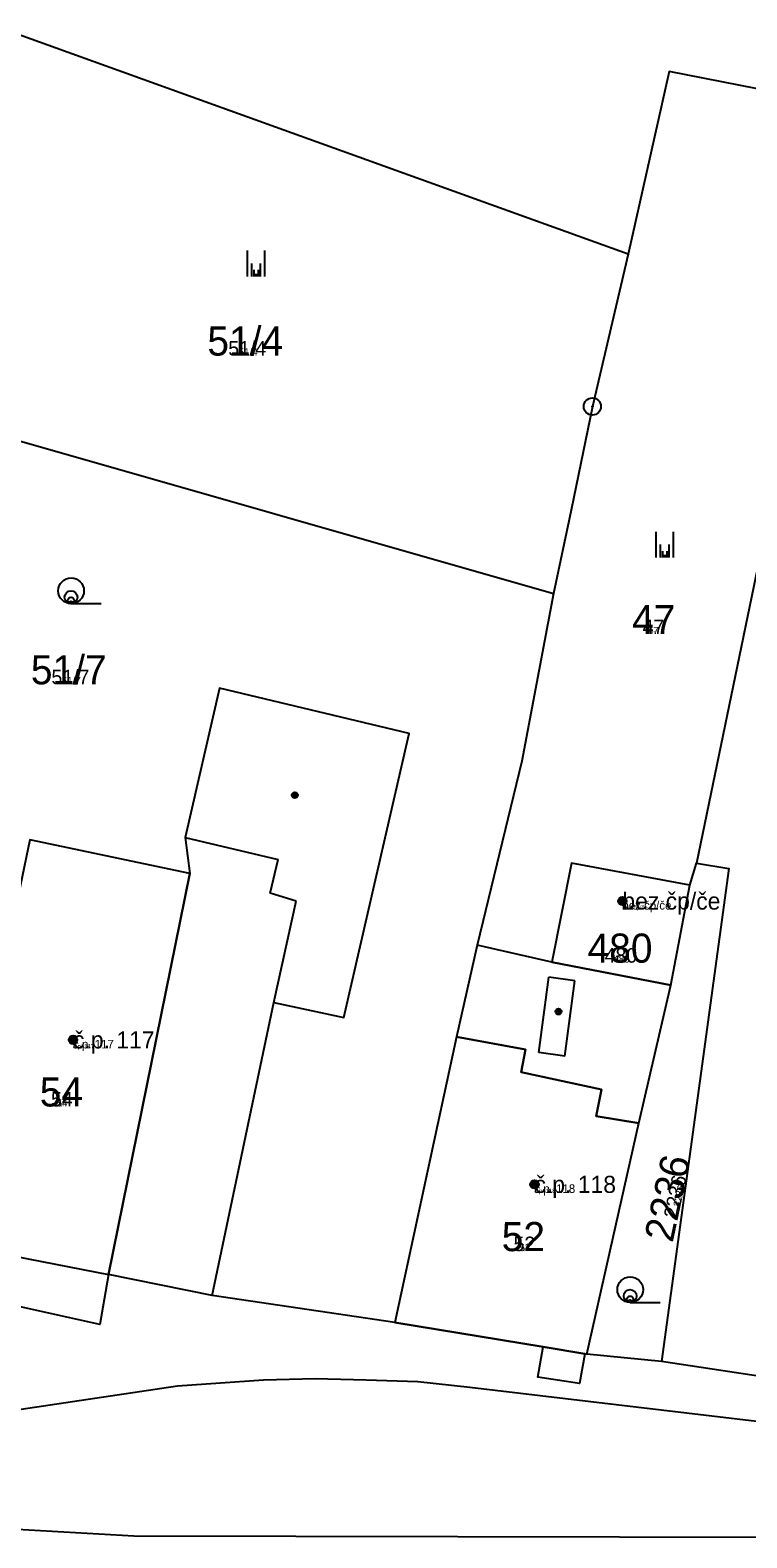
# Model space of a CAD drawing. Extents: x -744652 to -739090, y -980828 to -975855.
# Drawn here: x -742712.9 to -742671.1, y -978620.9 to -978532.9 of the extents above; entities that cross this region are included whole.
import ezdxf

# ---------------------------------------------------------------- set-up
doc = ezdxf.new("R2010")
doc.units = 0
for name, color, linetype in [('KAT_02_hranice parcel', 7, 'Continuous'), ('KAT_03_1000_st čísla parcelní', 7, 'Continuous'), ('KAT_03_1000_čísla parcelní', 7, 'Continuous'), ('KAT_03_1000_čísla popisná', 7, 'Continuous'), ('KAT_03_100_st čísla parcelní', 7, 'Continuous'), ('KAT_03_100_čísla parcelní', 7, 'Continuous'), ('KAT_03_100_čísla popisná', 7, 'Continuous'), ('KAT_03_250_st čísla parcelní', 7, 'Continuous'), ('KAT_03_250_čísla parcelní', 7, 'Continuous'), ('KAT_03_250_čísla popisná', 7, 'Continuous'), ('KAT_03_500_st čísla parcelní', 7, 'Continuous'), ('KAT_03_500_čísla parcelní', 7, 'Continuous'), ('KAT_03_500_čísla popisná', 7, 'Continuous'), ('KAT_04_vnitřní kresba', 7, 'Continuous'), ('KAT_05_1000_značky kultur', 7, 'Continuous'), ('KAT_05_100_značky kultur', 7, 'Continuous'), ('KAT_05_250_značky kultur', 7, 'Continuous'), ('KAT_05_500_značky kultur', 7, 'Continuous'), ('KAT_07_1000_značky budov', 7, 'Continuous'), ('KAT_07_100_značky budov', 7, 'Continuous'), ('KAT_07_500_značky budov', 7, 'Continuous'), ('KAT_10_věcná břemena', 7, 'Continuous'), ('KAT_11_značky bodu BP', 7, 'Continuous'), ('KAT_14_plocha_budovy', 7, 'Continuous')]:
    doc.layers.add(name, color=color, linetype=linetype)

msp = doc.modelspace()

# ---------------------------------------------------------------- linework, layer by layer
at = {"layer": 'KAT_02_hranice parcel'}
for p, q in [((-742678.03, -978545.97), (-742714.32, -978532.88)), ((-742720.83, -978554.79), (-742682.38, -978565.78)), ((-742674.42, -978582.82), (-742674.04, -978581.54)), ((-742675.53, -978588.66), (-742674.42, -978582.82)), ((-742682.48, -978587.32), (-742686.84, -978586.32)), ((-742675.53, -978588.66), (-742682.48, -978587.32)), ((-742702.3, -978606.79), (-742708.35, -978605.57)), ((-742691.64, -978608.37), (-742702.3, -978606.79)), ((-742676.07, -978610.64), (-742680.43, -978610.21)), ((-742670.16, -978611.55), (-742676.07, -978610.64))]:
    msp.add_line(p, q, dxfattribs=at)
for points in [[(-742655.01, -978539.34), (-742675.63, -978535.29), (-742678.03, -978545.97)], [(-742655.23, -978540.96), (-742665.24, -978538.98), (-742674.04, -978581.54)], [(-742678.03, -978545.97), (-742680.11, -978554.86), (-742681.34, -978560.91), (-742682.38, -978565.78)], [(-742682.38, -978565.78), (-742684.22, -978575.58), (-742686.84, -978586.32)], [(-742702.3, -978606.79), (-742698.7, -978589.67), (-742694.62, -978590.56), (-742690.81, -978573.96), (-742701.87, -978571.32), (-742703.87, -978580.04), (-742703.61, -978582.14), (-742712.95, -978580.17), (-742715.59, -978592.86), (-742716.86, -978592.62), (-742717.48, -978595.58), (-742716.2, -978595.84), (-742717.84, -978603.72), (-742708.35, -978605.57)], [(-742674.42, -978582.82), (-742681.32, -978581.54), (-742682.48, -978587.32)], [(-742674.04, -978581.54), (-742672.14, -978581.85), (-742676.07, -978610.64)], [(-742686.84, -978586.32), (-742688.04, -978591.69), (-742691.64, -978608.37)], [(-742680.43, -978610.21), (-742677.39, -978596.72), (-742675.53, -978588.66)], [(-742708.35, -978605.57), (-742708.85, -978608.48), (-742719.2, -978606.19)], [(-742680.43, -978610.21), (-742680.56, -978610.19), (-742680.87, -978611.94), (-742683.29, -978611.57), (-742682.99, -978609.79), (-742691.64, -978608.37)], [(-742522.65, -978636.07), (-742549.97, -978633.28), (-742570.9, -978630.86), (-742578.86, -978629.74), (-742582.72, -978630.81), (-742604.63, -978627.47), (-742606.59, -978627.11), (-742643.73, -978618.95), (-742648.55, -978617.06), (-742656.38, -978615.82), (-742687.27, -978612.16), (-742690.29, -978611.84), (-742693.32, -978611.73), (-742696.29, -978611.66), (-742699.31, -978611.74), (-742704.32, -978612.08), (-742722.21, -978614.75), (-742725.22, -978615.06), (-742728.22, -978615.18), (-742731.2, -978615.09), (-742734.19, -978614.83)]]:
    msp.add_lwpolyline(points, dxfattribs=at)
at = {"layer": 'KAT_03_1000_čísla popisná'}
for centre in [(-742678.36, -978583.75), (-742678.36, -978583.75), (-742710.42, -978591.86), (-742710.42, -978591.86), (-742683.49, -978600.3), (-742683.49, -978600.3)]:
    msp.add_circle(centre, 0.25, dxfattribs=at)
at = {"layer": 'KAT_03_100_čísla popisná'}
for centre in [(-742678.36, -978583.75), (-742678.36, -978583.75), (-742710.42, -978591.86), (-742710.42, -978591.86), (-742683.49, -978600.3), (-742683.49, -978600.3)]:
    msp.add_circle(centre, 0.025, dxfattribs=at)
at = {"layer": 'KAT_03_250_čísla popisná'}
for centre in [(-742678.36, -978583.75), (-742678.36, -978583.75), (-742710.42, -978591.86), (-742710.42, -978591.86), (-742683.49, -978600.3), (-742683.49, -978600.3)]:
    msp.add_circle(centre, 0.0625, dxfattribs=at)
at = {"layer": 'KAT_03_500_čísla popisná'}
for centre in [(-742678.36, -978583.75), (-742678.36, -978583.75), (-742710.42, -978591.86), (-742710.42, -978591.86), (-742683.49, -978600.3), (-742683.49, -978600.3)]:
    msp.add_circle(centre, 0.125, dxfattribs=at)
at = {"layer": 'KAT_04_vnitřní kresba'}
for p, q in [((-742703.87, -978580.04), (-742698.44, -978581.32)), ((-742703.61, -978582.14), (-742708.35, -978605.57)), ((-742698.92, -978583.29), (-742698.44, -978581.32)), ((-742697.39, -978583.76), (-742698.92, -978583.29)), ((-742698.7, -978589.67), (-742697.39, -978583.76)), ((-742683.23, -978592.59), (-742682.66, -978588.19)), ((-742681.14, -978588.42), (-742682.66, -978588.19)), ((-742681.71, -978592.82), (-742681.14, -978588.42)), ((-742688.04, -978591.69), (-742684.01, -978592.43)), ((-742684.01, -978592.43), (-742684.27, -978593.75)), ((-742681.71, -978592.82), (-742683.23, -978592.59)), ((-742684.27, -978593.75), (-742679.58, -978594.76)), ((-742679.58, -978594.76), (-742679.88, -978596.31)), ((-742679.88, -978596.31), (-742677.39, -978596.72)), ((-742680.56, -978610.19), (-742682.99, -978609.79))]:
    msp.add_line(p, q, dxfattribs=at)
at = {"layer": 'KAT_05_1000_značky kultur'}
for p, q in [((-742700.231, -978547.26), (-742700.231, -978545.76)), ((-742699.23, -978547.26), (-742699.23, -978545.76)), ((-742676.381, -978563.68), (-742676.381, -978562.18)), ((-742675.38, -978563.68), (-742675.38, -978562.18)), ((-742710.533, -978566.38), (-742708.783, -978566.38)), ((-742677.903, -978607.2), (-742676.153, -978607.2))]:
    msp.add_line(p, q, dxfattribs=at)
for centre in [(-742710.533, -978565.63), (-742677.903, -978606.45)]:
    msp.add_circle(centre, 0.75, dxfattribs=at)
at = {"layer": 'KAT_05_100_značky kultur'}
for p, q in [((-742699.771, -978547.26), (-742699.771, -978547.11)), ((-742699.671, -978547.26), (-742699.671, -978547.11)), ((-742675.921, -978563.68), (-742675.921, -978563.53)), ((-742675.821, -978563.68), (-742675.821, -978563.53)), ((-742710.539, -978566.38), (-742710.364, -978566.38)), ((-742677.909, -978607.2), (-742677.734, -978607.2))]:
    msp.add_line(p, q, dxfattribs=at)
for centre in [(-742710.539, -978566.305), (-742677.909, -978607.125)]:
    msp.add_circle(centre, 0.075, dxfattribs=at)
at = {"layer": 'KAT_05_250_značky kultur'}
for p, q in [((-742699.848, -978547.26), (-742699.848, -978546.885)), ((-742699.598, -978547.26), (-742699.598, -978546.885)), ((-742675.998, -978563.68), (-742675.998, -978563.305)), ((-742675.748, -978563.68), (-742675.748, -978563.305)), ((-742710.538, -978566.38), (-742710.101, -978566.38)), ((-742677.908, -978607.2), (-742677.471, -978607.2))]:
    msp.add_line(p, q, dxfattribs=at)
for centre in [(-742710.538, -978566.192), (-742677.908, -978607.012)]:
    msp.add_circle(centre, 0.187, dxfattribs=at)
at = {"layer": 'KAT_05_500_značky kultur'}
for p, q in [((-742699.976, -978547.26), (-742699.976, -978546.51)), ((-742699.475, -978547.26), (-742699.475, -978546.51)), ((-742676.125, -978563.68), (-742676.125, -978562.93)), ((-742675.625, -978563.68), (-742675.625, -978562.93)), ((-742710.537, -978566.38), (-742709.662, -978566.38)), ((-742677.907, -978607.2), (-742677.032, -978607.2))]:
    msp.add_line(p, q, dxfattribs=at)
for centre in [(-742710.536, -978566.005), (-742677.906, -978606.825)]:
    msp.add_circle(centre, 0.375, dxfattribs=at)
at = {"layer": 'KAT_07_1000_značky budov'}
for centre in [(-742697.477, -978577.569), (-742678.367, -978583.749), (-742682.087, -978590.209), (-742710.427, -978591.859), (-742683.497, -978600.299)]:
    msp.add_circle(centre, 0.175, dxfattribs=at)
at = {"layer": 'KAT_07_100_značky budov'}
for centre in [(-742697.471, -978577.57), (-742678.361, -978583.75), (-742682.081, -978590.21), (-742710.421, -978591.86), (-742683.491, -978600.3)]:
    msp.add_circle(centre, 0.0175, dxfattribs=at)
at = {"layer": 'KAT_07_500_značky budov'}
for centre, radius in [((-742697.473, -978577.57), 0.0875), ((-742697.472, -978577.57), 0.0438), ((-742678.363, -978583.75), 0.0875), ((-742678.362, -978583.75), 0.0438), ((-742682.083, -978590.21), 0.0875), ((-742682.082, -978590.21), 0.0438), ((-742710.423, -978591.86), 0.0875), ((-742710.422, -978591.86), 0.0438), ((-742683.493, -978600.3), 0.0875), ((-742683.492, -978600.3), 0.0438)]:
    msp.add_circle(centre, radius, dxfattribs=at)
at = {"layer": 'KAT_10_věcná břemena'}
msp.add_lwpolyline([(-742612.55, -978632.12), (-742641.67, -978624.81), (-742669.08, -978620.92), (-742706.88, -978620.85), (-742736.16, -978619.17), (-742737.02, -978621.05), (-742706.92, -978622.05), (-742669.16, -978622.12), (-742641.91, -978625.99), (-742612.75, -978633.3)], dxfattribs=at)
at = {"layer": 'KAT_11_značky bodu BP'}
for radius in [0.5, 0.0303]:
    msp.add_circle((-742680.11, -978554.86), radius, dxfattribs=at)
at = {"layer": 'KAT_14_plocha_budovy'}
for points in [[(-742715.59, -978592.86), (-742716.86, -978592.62), (-742717.48, -978595.58), (-742716.2, -978595.84), (-742717.84, -978603.72), (-742708.35, -978605.57), (-742703.61, -978582.14), (-742712.95, -978580.17)], [(-742682.48, -978587.32), (-742675.53, -978588.66), (-742674.42, -978582.82), (-742681.32, -978581.54)], [(-742682.99, -978609.79), (-742680.56, -978610.19), (-742680.43, -978610.21), (-742677.39, -978596.72), (-742679.88, -978596.31), (-742679.58, -978594.76), (-742684.27, -978593.75), (-742684.01, -978592.43), (-742688.04, -978591.69), (-742691.64, -978608.37)]]:
    msp.add_lwpolyline(points, close=True, dxfattribs=at)

# ---------------------------------------------------------------- texts
at = {"layer": 'KAT_03_1000_st čísla parcelní'}
for s, p in [('480', (-742680.394, -978587.35)), ('54', (-742712.362, -978595.75)), ('52', (-742685.402, -978604.2))]:
    msp.add_text(s, height=1.7, dxfattribs=at).set_placement(p)
at = {"layer": 'KAT_03_1000_čísla parcelní'}
for s, p in [('51/4', (-742702.581, -978551.89)), ('47', (-742677.792, -978568.16)), ('51/7', (-742712.881, -978571.09))]:
    msp.add_text(s, height=1.7, dxfattribs=at).set_placement(p)
msp.add_text('2236', height=1.7, rotation=78, dxfattribs=at).set_placement((-742675.429, -978603.749))
at = {"layer": 'KAT_03_1000_čísla popisná'}
for s, height, p in [('bez čp/če', 1, (-742678.36, -978584.25)), ('480', 0.017, (-742678.406, -978587.35)), ('č.p. 117', 1, (-742710.42, -978592.36)), ('54', 0.017, (-742711.063, -978595.75)), ('č.p. 118', 1, (-742683.49, -978600.8)), ('52', 0.017, (-742684.03, -978604.2))]:
    msp.add_text(s, height=height, dxfattribs=at).set_placement(p)
at = {"layer": 'KAT_03_100_st čísla parcelní'}
for s, p in [('480', (-742678.587, -978587.35)), ('54', (-742711.181, -978595.75)), ('52', (-742684.155, -978604.2))]:
    msp.add_text(s, height=0.17, dxfattribs=at).set_placement(p)
at = {"layer": 'KAT_03_100_čísla parcelní'}
for s, p in [('51/4', (-742700.383, -978551.89)), ('47', (-742676.69, -978568.16)), ('51/7', (-742710.719, -978571.09))]:
    msp.add_text(s, height=0.17, dxfattribs=at).set_placement(p)
msp.add_text('2236', height=0.17, rotation=78, dxfattribs=at).set_placement((-742674.891, -978601.216))
at = {"layer": 'KAT_03_100_čísla popisná'}
for s, height, p in [('bez čp/če', 0.1, (-742678.36, -978584.25)), ('480', 0.0017, (-742678.388, -978587.35)), ('č.p. 117', 0.1, (-742710.42, -978592.36)), ('54', 0.0017, (-742711.052, -978595.75)), ('č.p. 118', 0.1, (-742683.49, -978600.8)), ('52', 0.0017, (-742684.018, -978604.2))]:
    msp.add_text(s, height=height, dxfattribs=at).set_placement(p)
at = {"layer": 'KAT_03_250_st čísla parcelní'}
for s, p in [('480', (-742678.888, -978587.35)), ('54', (-742711.378, -978595.75)), ('52', (-742684.363, -978604.2))]:
    msp.add_text(s, height=0.425, dxfattribs=at).set_placement(p)
at = {"layer": 'KAT_03_250_čísla parcelní'}
for s, p in [('51/4', (-742700.749, -978551.89)), ('47', (-742676.873, -978568.16)), ('51/7', (-742711.079, -978571.09))]:
    msp.add_text(s, height=0.425, dxfattribs=at).set_placement(p)
msp.add_text('2236', height=0.425, rotation=78, dxfattribs=at).set_placement((-742674.98, -978601.638))
at = {"layer": 'KAT_03_250_čísla popisná'}
for s, height, p in [('bez čp/če', 0.25, (-742678.36, -978584.25)), ('480', 0.00425, (-742678.391, -978587.35)), ('č.p. 117', 0.25, (-742710.42, -978592.36)), ('54', 0.00425, (-742711.054, -978595.75)), ('č.p. 118', 0.25, (-742683.49, -978600.8)), ('52', 0.00425, (-742684.02, -978604.2))]:
    msp.add_text(s, height=height, dxfattribs=at).set_placement(p)
at = {"layer": 'KAT_03_500_st čísla parcelní'}
for s, p in [('480', (-742679.39, -978587.35)), ('54', (-742711.706, -978595.75)), ('52', (-742684.709, -978604.2))]:
    msp.add_text(s, height=0.85, dxfattribs=at).set_placement(p)
at = {"layer": 'KAT_03_500_čísla parcelní'}
for s, p in [('51/4', (-742701.36, -978551.89)), ('47', (-742677.18, -978568.16)), ('51/7', (-742711.68, -978571.09))]:
    msp.add_text(s, height=0.85, dxfattribs=at).set_placement(p)
msp.add_text('2236', height=0.85, rotation=78, dxfattribs=at).set_placement((-742675.13, -978602.342))
at = {"layer": 'KAT_03_500_čísla popisná'}
for s, height, p in [('bez čp/če', 0.5, (-742678.36, -978584.25)), ('480', 0.0085, (-742678.396, -978587.35)), ('č.p. 117', 0.5, (-742710.42, -978592.36)), ('54', 0.0085, (-742711.057, -978595.75)), ('č.p. 118', 0.5, (-742683.49, -978600.8)), ('52', 0.0085, (-742684.024, -978604.2))]:
    msp.add_text(s, height=height, dxfattribs=at).set_placement(p)

doc.saveas('drawing.dxf')
